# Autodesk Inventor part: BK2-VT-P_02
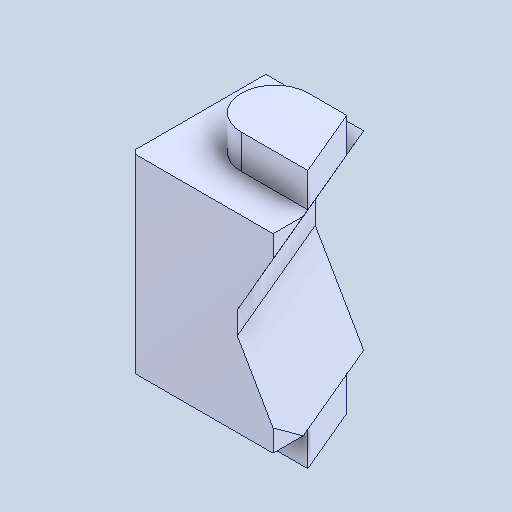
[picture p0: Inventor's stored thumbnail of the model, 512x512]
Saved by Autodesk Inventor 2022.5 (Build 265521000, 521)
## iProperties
Created: 2024-08
Part Number: BK2-VT-P_02
Material: 一般
Document SubType Name: Modeling
Designer: ImaoCorp
Density: 1 g/cm^3
Appearance: 既定
Author: ImaoCorp
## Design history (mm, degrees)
feature "BK2-VT-P_02"
node "ソリッド1"
